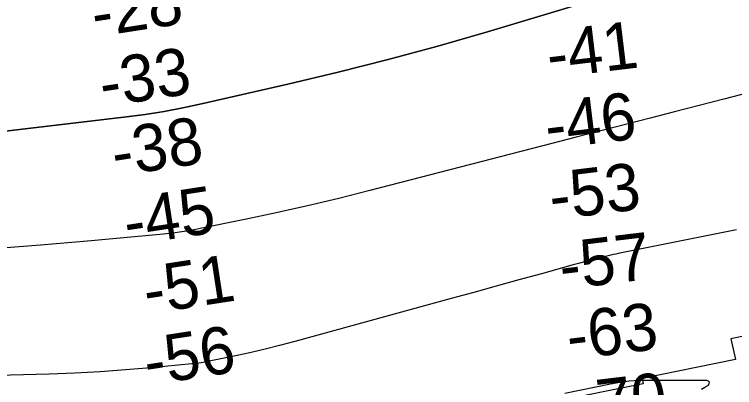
# Model space of a CAD drawing. Extents: x 3281947 to 3319794, y 715894 to 741249.
# Drawn here: x 3302354 to 3303376, y 728397 to 728927 of the extents above; entities that cross this region are included whole.
import ezdxf

# ---------------------------------------------------------------- set-up
doc = ezdxf.new("R2010")
doc.units = 0
for name, color, linetype in [('V-RIVR-RANG', 7, 'Continuous'), ('V-RRAP-RVMT', 7, 'Continuous'), ('V-TOPO-DPTH', 7, 'Continuous'), ('V-TOPO-MAJR', 7, 'Continuous'), ('V-TOPO-MINR', 7, 'Continuous')]:
    doc.layers.add(name, color=color, linetype=linetype)

msp = doc.modelspace()

# ---------------------------------------------------------------- linework, layer by layer
at = {"layer": 'V-RRAP-RVMT'}
msp.add_lwpolyline([(3303513.1, 728496.8), (3303370.9, 728466.3), (3303377.3, 728437.3), (3303245, 728410), (3303246.6, 728402.4), (3303114.6, 728376.2), (3303116.4, 728366.6), (3302982.6, 728342.9), (3302985.1, 728328.9), (3302861.1, 728306.2), (3302858.8, 728319.3), (3302719.4, 728293.1), (3302722.8, 728274.8), (3302602.6, 728253.4), (3302603.9, 728245.6), (3302475.3, 728219.2), (3302477.6, 728208.7), (3302345.1, 728184.9), (3302347.3, 728172.2), (3302231.5, 728151.2), (3302234.3, 728135.7), (3302083, 728106.6)], dxfattribs=at)
at = {"layer": 'V-TOPO-DPTH'}
for points in [[(3303413.6, 729019.4), (3303364.1, 729004.1), (3303314.5, 728989), (3303264.9, 728974), (3303196.8, 728953.6), (3303181.2, 728948.9), (3303165.6, 728944.2), (3303150, 728939.5), (3303134.4, 728934.9), (3303025.4, 728902.3), (3302955.1, 728882), (3302884.5, 728862.7), (3302813.6, 728844.8), (3302742.4, 728827.8), (3302619.9, 728799.8), (3302593.4, 728794.2), (3302566.8, 728789.1), (3302540.1, 728785), (3302513.2, 728781.4), (3301861.7, 728704.3)], [(3301861.7, 728704.3), (3302513.2, 728781.4), (3302540.1, 728785), (3302566.8, 728789.1), (3302593.4, 728794.2), (3302619.9, 728799.8), (3302742.4, 728827.8), (3302813.6, 728844.8), (3302884.5, 728862.7), (3302955.1, 728882), (3303025.4, 728902.3), (3303134.4, 728934.9), (3303150, 728939.5), (3303165.6, 728944.2), (3303181.2, 728948.9), (3303196.8, 728953.6), (3303264.9, 728974), (3303314.5, 728989), (3303364.1, 729004.1), (3303413.6, 729019.4)]]:
    msp.add_lwpolyline(points, dxfattribs=at)
at = {"layer": 'V-TOPO-MAJR'}
msp.add_lwpolyline([(3303395.6, 728815.5), (3303360.8, 728806.4), (3303325.9, 728797.4), (3303291, 728788.4), (3303256.2, 728779.6), (3303221.3, 728770.7), (3303186.4, 728761.7), (3303151.5, 728752.8), (3303116.7, 728743.8), (3302858.7, 728676.8), (3302814.6, 728665.8), (3302770.3, 728655.1), (3302725.9, 728645.2), (3302681.4, 728635.8), (3302617.9, 728622.8), (3302605, 728620.4), (3302592.1, 728618.2), (3302579.1, 728616.5), (3302566.1, 728615.1), (3302458.2, 728605), (3302391.2, 728599.2), (3302324.1, 728594.1)], dxfattribs=at)
at = {"layer": 'V-TOPO-MINR'}
for points in [[(3303413.6, 729019.4), (3303364.1, 729004.1), (3303314.5, 728989), (3303264.9, 728974), (3303196.8, 728953.6), (3303181.2, 728948.9), (3303165.6, 728944.2), (3303150, 728939.5), (3303134.4, 728934.9), (3303025.4, 728902.3), (3302955.1, 728882), (3302884.5, 728862.7), (3302813.6, 728844.8), (3302742.4, 728827.8), (3302619.9, 728799.8), (3302593.4, 728794.2), (3302566.8, 728789.1), (3302540.1, 728785), (3302513.2, 728781.4), (3301861.7, 728704.3)], [(3303378.9, 728621), (3303211.1, 728587.6), (3303207.5, 728586.8), (3303203.9, 728586), (3303200.4, 728585.2), (3303196.8, 728584.4), (3303185, 728581.4), (3303175.5, 728579), (3303166.1, 728576.5), (3303156.6, 728574), (3303147.2, 728571.4), (3303102, 728558.8), (3303070, 728550), (3303038, 728541.1), (3303006, 728532.3), (3302974, 728523.5), (3302752.2, 728462.8), (3302730.3, 728457), (3302708.3, 728451.5), (3302686.2, 728446.3), (3302664, 728441.5), (3302632.9, 728435), (3302626.2, 728433.7), (3302619.5, 728432.5), (3302612.8, 728431.6), (3302606, 728430.9), (3302547.8, 728425.2), (3302511.9, 728422.2), (3302475.9, 728419.6), (3302439.9, 728417.8), (3302403.9, 728416.5), (3302128.8, 728409.4)], [(3303329.2, 728395.2), (3303334.1, 728397.9), (3303339, 728400.9), (3303340.2, 728403), (3303340.4, 728404.8), (3303339.2, 728406.2), (3303337, 728407.3), (3303254, 728407.5), (3303240.4, 728407.1), (3303226.8, 728406.2), (3303213.4, 728404.4), (3303199.9, 728402.1), (3303135.4, 728388.8)]]:
    msp.add_lwpolyline(points, dxfattribs=at)

# ---------------------------------------------------------------- texts
at = {"layer": 'V-RIVR-RANG'}
for s, rotation, p in [('-28', 8.7776, (3302468.6, 728894.6)), ('-41', 6.9039, (3303113.4, 728836.2)), ('-33', 8.7776, (3302480, 728795.2)), ('-46', 6.9039, (3303110.8, 728735.2)), ('-38', 8.7776, (3302497.3, 728696.7)), ('-53', 6.9039, (3303116.9, 728635.2)), ('-45', 8.7776, (3302514.5, 728598.2)), ('-57', 6.9039, (3303131.3, 728536.2)), ('-51', 8.7776, (3302542.4, 728501.3)), ('-63', 6.9039, (3303141.6, 728436.7)), ('-56', 8.7776, (3302543.2, 728400.2)), ('-70', 6.9039, (3303154.7, 728337.6))]:
    msp.add_text(s, height=67, rotation=rotation, dxfattribs=at).set_placement(p)

doc.saveas('drawing.dxf')
